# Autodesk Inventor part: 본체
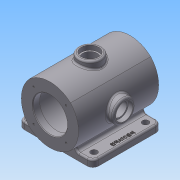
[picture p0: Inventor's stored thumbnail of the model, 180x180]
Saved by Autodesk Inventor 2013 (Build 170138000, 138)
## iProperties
Company: 한국ATC센터
Created: 2014-08
Part Number: 본체
Document SubType Name: Modeling
Designer: KYOUNG IL JANG
Density: 2.71 g/cm^3
Material: 알루미늄 6061
Mass: 1882.17 g
Surface Area: 1142.37 cm^2
Volume: 694.527 cm^3
Author: KYOUNG IL JANG
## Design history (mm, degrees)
sketch "스케치1"
  geometry: L1 (-50, 0)-(50, 0); L2 (-36.062, 36.062)-(36.062, 36.062); L3 (36.062, 36.062)-(36.062, -36.062); L4 (36.062, -36.062)-(-36.062, -36.062); L5 (-36.062, -36.062)-(-36.062, 36.062); A1 r 53.623 centre (-3.623, 0) between (36.062, -36.062) and (36.062, 36.062); A2 r 53.623 centre (3.623, 0) between (-36.062, 36.062) and (-36.062, -36.062); A3 r 53.623 centre (0, -3.623) between (36.062, 36.062) and (-36.062, 36.062); A4 r 53.623 centre (0, 3.623) between (-36.062, -36.062) and (36.062, -36.062); 4 further points
  constraints: 11 point on circle, 10 end point, 5 coincident, 4 centre point, 4 horizontal alignment, 3 equal radius, 2 horizontal, 2 parallel, 2 perpendicular, 1 midpoint
  dimensions: "d83" = 51 distance of L2.end point (0, 0); "d84" = 100 distance of L1.end L1.start
extrude "돌출1" new body sketch "스케치1" stored distance "d9" = 140; taper "d10" = 0 deg
node "작업 평면1"
sketch "스케치2"
  geometry: L1 (65, 60)-(-65, 60); L2 (-65, 60)-(-65, -60); L3 (-65, -60)-(65, -60); L4 (65, -60)-(65, 60); 4 further points
  constraints: 8 end point, 3 midpoint, 2 parallel, 2 vertical alignment, 1 horizontal, 1 horizontal alignment, 1 perpendicular
  dimensions: "d14" = 130 distance of L2.end L3.end; "d82" = 120 distance of L1.end L2.end
extrude "돌출2" join sketch "스케치2" distance "d15" = 12; taper "d16" = 0 deg
node "작업 평면3"
  node "작업 평면4"
sketch "스케치3"
  geometry: C1 r 20 at (0, 0); 1 further point
  constraints: 2 coincident, 1 centre point
  dimensions: "d19" = 40 diameter of C1
extrude "돌출3" join sketch "스케치3" stored distance "d23" = 12; taper "d24" = 0 deg
node "작업 평면6"
  node "작업 평면5"
sketch "스케치13"
  geometry: C1 r 20 at (0, 0); 1 further point
  constraints: 1 centre point, 1 coincident
  dimensions: "d88" = 40 diameter of C1
extrude "돌출7" join sketch "스케치13" stored distance "d89" = 10; taper "d90" = 0 deg
sketch "스케치4"
  geometry: C1 r 37.5 at (0, 0); 1 further point
  constraints: 1 centre point, 1 coincident
  dimensions: "d25" = 75 diameter of C1
extrude "돌출4" cut sketch "스케치4" stored distance "d26" = 116; taper "d27" = 0 deg
sketch "스케치5"
  geometry: C1 r 30 at (0, 0); 1 further point
  constraints: 1 centre point, 1 coincident
  dimensions: "d28" = 60 diameter of C1
extrude "돌출5" cut sketch "스케치5" stored distance "d29" = 116; taper "d30" = 0 deg
hole "구멍1" diameter "d33" = 25; stored, may be unused: countersink angle "d37" = 90 deg, drill point angle "d39" = 0 deg; dims "d31" = 10, "d32" = 10, "d34" = 6, "d35" = 30, "d36" = 8, "d38" = 40
hole "구멍4" diameter "d93" = 25; stored, may be unused: countersink angle "d97" = 90 deg, drill point angle "d99" = 118 deg; dims "d91" = 10, "d92" = 10, "d94" = 6, "d95" = 30, "d96" = 8, "d98" = 8
sketch "스케치6"
  geometry: L1 (-65, -60)-(-65, 60) reference; L2 (-65, 60)-(65, 60) reference; L3 (65, -60)-(-65, -60) reference; L4 (65, 60)-(65, -60) reference; L5 (0, -60)-(0, 60); L6 (-65, 0)-(65, 0); L7 (-52, -45)-(52, 45); C1 r 5.5 at (-52, -45); C2 r 5.5 at (-52, 45); C3 r 5.5 at (52, -45); C4 r 5.5 at (52, 45); 2 further points
  constraints: 6 end point, 6 midpoint, 4 centre point, 2 equal radius, 2 horizontal alignment, 2 vertical alignment
  dimensions: "d49" = 11 diameter of C1; "d50" = 11 diameter of C2; "d51" = 104 distance of L7.end C2.centre; "d52" = 90 distance of C3.centre L7.end
extrude "돌출6" cut sketch "스케치6" distance "d53" = 116; taper "d54" = 0 deg
sketch "스케치8"
  geometry: L1 (65, 60)-(65, -60) reference; 2 further points
  constraints: 1 horizontal alignment, 1 other
  dimensions: "d55" = 8 distance from line of L1 point (57, 0)
feature "엠보싱1" sketch "스케치8" dims "d27" = 0, "d57" = 1, "d58" = 0
fillet "모깎기2" dims "d60" = 5
fillet "모깎기5" dims "d63" = 10
fillet "모깎기6" dims "d64" = 3
fillet "모깎기7" dims "d65" = 3
sketch "스케치9"
  geometry: L1 (0, 0)-(-28.284, 28.284); L2 (0, 0)-(0, 40); C1 r 30 at (0, 0) reference; A1 r 40 centre (0, 0) between (-28.284, 28.284) and (0, 40); 1 further point
  constraints: 4 end point, 2 coincident, 2 point on circle, 1 centre point, 1 vertical
  dimensions: "d66" = 80 diameter of A1; "d67" = 45 deg angle of L1 L2
hole "M4" sketch "스케치9" at (-28.284, 28.284) diameter "d68" = 3.242; stored, may be unused: countersink angle "d72" = 90 deg, drill point angle "d74" = 118 deg; dims "d69" = 8, "d70" = 30, "d71" = 8, "d73" = 10
fillet "모깎기8" dims "d78" = 3
chamfer "모따기1" distance "d79" = 1; stored, may be unused: second distance "d80" = 2, angle "d81" = 45 deg
node "솔리드1"
pattern_circular "원형 패턴1" dims angle "d76" = 360 deg
mirror "대칭1"
other parameters: "d11" = -55
